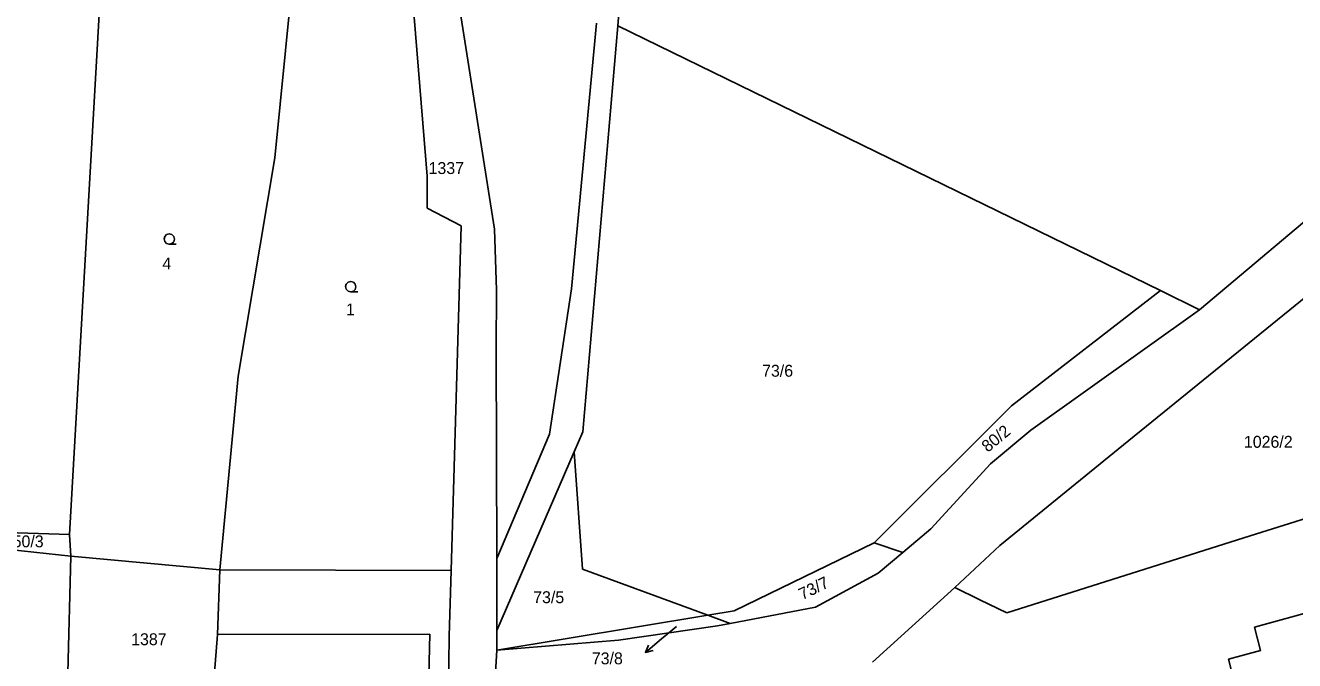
# Model space of a CAD drawing. Extents: x -852001 to -842497, y -1063614 to -1052182.
# Drawn here: x -844444 to -844262.9, y -1061413.7 to -1061323.1 of the extents above; entities that cross this region are included whole.
import ezdxf

# ---------------------------------------------------------------- set-up
doc = ezdxf.new("R2010")
doc.units = 0
for name, color, linetype in [('Default', 7, 'Continuous'), ('KN_HRANICE', 7, 'Continuous'), ('KN_KULTURY', 7, 'Continuous'), ('KN_PARCELY', 7, 'Continuous'), ('KN_SLUCKY', 7, 'Continuous')]:
    doc.layers.add(name, color=color, linetype=linetype)

# ---------------------------------------------------------------- blocks, each defined once
blk = doc.blocks.new('304')
at = {"layer": 'Default'}
blk.add_lwpolyline([(0, 0), (-0.38, 0.1), (-0.65, 0.37), (-0.75, 0.74), (-0.65, 1.11), (-0.38, 1.38), (-0.01, 1.48), (0.36, 1.38), (0.63, 1.11), (0.73, 0.73), (0.63, 0.35), (0.36, 0.08), (-0.02, -0.02), (0.98, -0.02)], dxfattribs=at)
blk = doc.blocks.new('10292')
at = {"layer": 'Default'}
blk.add_line((0, 3), (0, 0), dxfattribs=at)
blk.add_lwpolyline([(-0.5, 2), (0, 3), (0.5, 2)], dxfattribs=at)

msp = doc.modelspace()

# ---------------------------------------------------------------- linework, layer by layer
at = {"layer": 'KN_HRANICE'}
for p, q in [((-844355.8, -1061278.6), (-844359.49, -1061323.11)), ((-844355.8, -1061278.6), (-844359.49, -1061323.11)), ((-844437.76, -1061395.7), (-844432.89, -1061310.51)), ((-844437.76, -1061395.7), (-844432.89, -1061310.51)), ((-844408.43, -1061341.94), (-844405.53, -1061312.84)), ((-844408.43, -1061341.94), (-844405.53, -1061312.84)), ((-844389.08, -1061315.26), (-844386.69, -1061344.57)), ((-844389.08, -1061315.26), (-844386.69, -1061344.57)), ((-844377.08, -1061352.12), (-844382.88, -1061315.51)), ((-844377.08, -1061352.12), (-844382.88, -1061315.51)), ((-844362.55, -1061322.76), (-844366.12, -1061360.65)), ((-844362.55, -1061322.76), (-844366.12, -1061360.65)), ((-844359.49, -1061323.11), (-844364.48, -1061381.09)), ((-844359.49, -1061323.11), (-844364.48, -1061381.09)), ((-844282.06, -1061360.88), (-844359.49, -1061323.11)), ((-844282.06, -1061360.88), (-844359.49, -1061323.11)), ((-844276.49, -1061363.63), (-844241.6, -1061334.29)), ((-844276.49, -1061363.63), (-844241.6, -1061334.29)), ((-844413.69, -1061373.1), (-844408.43, -1061341.94)), ((-844413.69, -1061373.1), (-844408.43, -1061341.94)), ((-844386.69, -1061344.57), (-844386.69, -1061349.14)), ((-844386.69, -1061344.57), (-844386.69, -1061349.14)), ((-844386.69, -1061349.14), (-844381.84, -1061351.65)), ((-844386.69, -1061349.14), (-844381.84, -1061351.65)), ((-844381.84, -1061351.65), (-844383.28, -1061400.88)), ((-844381.84, -1061351.65), (-844383.28, -1061400.88)), ((-844376.79, -1061360.87), (-844377.08, -1061352.12)), ((-844376.79, -1061360.87), (-844377.08, -1061352.12)), ((-844255.48, -1061357.05), (-844287.3, -1061382.9)), ((-844255.48, -1061357.05), (-844287.3, -1061382.9)), ((-844376.86, -1061369.32), (-844376.79, -1061360.87)), ((-844376.86, -1061369.32), (-844376.79, -1061360.87)), ((-844366.12, -1061360.65), (-844369.26, -1061381.41)), ((-844366.12, -1061360.65), (-844369.26, -1061381.41)), ((-844282.06, -1061360.88), (-844303.29, -1061377.34)), ((-844282.06, -1061360.88), (-844303.29, -1061377.34)), ((-844282.06, -1061360.88), (-844276.49, -1061363.63)), ((-844282.06, -1061360.88), (-844276.49, -1061363.63)), ((-844300.54, -1061380.81), (-844276.49, -1061363.63)), ((-844300.54, -1061380.81), (-844276.49, -1061363.63)), ((-844376.78, -1061399.14), (-844376.86, -1061369.32)), ((-844376.78, -1061399.14), (-844376.86, -1061369.32)), ((-844416.28, -1061400.77), (-844413.69, -1061373.1)), ((-844416.28, -1061400.77), (-844413.69, -1061373.1)), ((-844303.29, -1061377.34), (-844322.91, -1061396.91)), ((-844303.29, -1061377.34), (-844322.91, -1061396.91)), ((-844306.31, -1061385.64), (-844300.54, -1061380.81)), ((-844306.31, -1061385.64), (-844300.54, -1061380.81)), ((-844369.26, -1061381.41), (-844376.78, -1061399.14)), ((-844369.26, -1061381.41), (-844376.78, -1061399.14)), ((-844364.48, -1061381.09), (-844365.7, -1061383.91)), ((-844364.48, -1061381.09), (-844365.7, -1061383.91)), ((-844365.7, -1061383.91), (-844376.75, -1061409.41)), ((-844365.7, -1061383.91), (-844376.75, -1061409.41)), ((-844365.7, -1061383.91), (-844364.51, -1061400.66)), ((-844365.7, -1061383.91), (-844364.51, -1061400.66)), ((-844287.3, -1061382.9), (-844304.99, -1061397.3)), ((-844287.3, -1061382.9), (-844304.99, -1061397.3)), ((-844314.83, -1061394.93), (-844306.31, -1061385.64)), ((-844314.83, -1061394.93), (-844306.31, -1061385.64)), ((-844234.19, -1061384.88), (-844269.23, -1061395.89)), ((-844234.19, -1061384.88), (-844269.23, -1061395.89)), ((-844475.97, -1061394.54), (-844437.76, -1061395.7)), ((-844437.56, -1061398.83), (-844475.97, -1061394.54)), ((-844475.97, -1061394.54), (-844437.76, -1061395.7)), ((-844437.56, -1061398.83), (-844475.97, -1061394.54)), ((-844318.83, -1061398.3), (-844314.83, -1061394.93)), ((-844318.83, -1061398.3), (-844314.83, -1061394.93)), ((-844437.56, -1061398.83), (-844437.76, -1061395.7)), ((-844437.56, -1061398.83), (-844437.76, -1061395.7)), ((-844322.91, -1061396.91), (-844342.88, -1061406.62)), ((-844322.91, -1061396.91), (-844342.88, -1061406.62)), ((-844322.91, -1061396.91), (-844318.83, -1061398.3)), ((-844322.91, -1061396.91), (-844318.83, -1061398.3)), ((-844269.23, -1061395.89), (-844303.98, -1061406.9)), ((-844269.23, -1061395.89), (-844303.98, -1061406.9)), ((-844438.01, -1061415.47), (-844437.56, -1061398.83)), ((-844438.01, -1061415.47), (-844437.56, -1061398.83)), ((-844437.56, -1061398.83), (-844416.28, -1061400.77)), ((-844437.56, -1061398.83), (-844416.28, -1061400.77)), ((-844322.33, -1061401.24), (-844318.83, -1061398.3)), ((-844322.33, -1061401.24), (-844318.83, -1061398.3)), ((-844304.99, -1061397.3), (-844311.38, -1061403.28)), ((-844304.99, -1061397.3), (-844311.38, -1061403.28)), ((-844416.28, -1061400.77), (-844416.62, -1061410.01)), ((-844416.28, -1061400.77), (-844416.62, -1061410.01)), ((-844416.28, -1061400.77), (-844383.28, -1061400.88)), ((-844416.28, -1061400.77), (-844383.28, -1061400.88)), ((-844376.75, -1061409.41), (-844376.78, -1061399.14)), ((-844376.75, -1061409.41), (-844376.78, -1061399.14)), ((-844364.51, -1061400.66), (-844346.64, -1061407.24)), ((-844364.51, -1061400.66), (-844346.64, -1061407.24)), ((-844383.28, -1061400.88), (-844383.55, -1061410.22)), ((-844383.28, -1061400.88), (-844383.55, -1061410.22)), ((-844331.28, -1061406.1), (-844322.33, -1061401.24)), ((-844331.28, -1061406.1), (-844322.33, -1061401.24)), ((-844311.38, -1061403.28), (-844323.12, -1061413.92)), ((-844311.38, -1061403.28), (-844323.12, -1061413.92)), ((-844307.8, -1061405.03), (-844311.38, -1061403.28)), ((-844307.8, -1061405.03), (-844311.38, -1061403.28)), ((-844343.46, -1061408.4), (-844331.28, -1061406.1)), ((-844343.46, -1061408.4), (-844331.28, -1061406.1)), ((-844303.98, -1061406.9), (-844307.8, -1061405.03)), ((-844303.98, -1061406.9), (-844307.8, -1061405.03)), ((-844346.64, -1061407.24), (-844376.75, -1061412.24)), ((-844346.64, -1061407.24), (-844376.75, -1061412.24)), ((-844342.88, -1061406.62), (-844346.64, -1061407.24)), ((-844342.88, -1061406.62), (-844346.64, -1061407.24)), ((-844346.64, -1061407.24), (-844343.46, -1061408.4)), ((-844346.64, -1061407.24), (-844343.46, -1061408.4)), ((-844259.62, -1061406.48), (-844268.64, -1061408.96)), ((-844259.62, -1061406.48), (-844268.64, -1061408.96)), ((-844376.75, -1061409.41), (-844376.75, -1061412.24)), ((-844376.75, -1061409.41), (-844376.75, -1061412.24)), ((-844359.4, -1061410.79), (-844345.26, -1061408.74)), ((-844359.4, -1061410.79), (-844345.26, -1061408.74)), ((-844345.26, -1061408.74), (-844343.46, -1061408.4)), ((-844345.26, -1061408.74), (-844343.46, -1061408.4)), ((-844267.77, -1061412.3), (-844268.64, -1061408.96)), ((-844267.77, -1061412.3), (-844268.64, -1061408.96)), ((-844416.62, -1061410.01), (-844417.56, -1061421.43)), ((-844416.62, -1061410.01), (-844417.56, -1061421.43)), ((-844383.55, -1061410.22), (-844383.68, -1061421.62)), ((-844383.55, -1061410.22), (-844383.68, -1061421.62)), ((-844376.75, -1061412.24), (-844359.4, -1061410.79)), ((-844376.75, -1061412.24), (-844359.4, -1061410.79)), ((-844377.11, -1061418.19), (-844376.75, -1061412.24)), ((-844377.11, -1061418.19), (-844376.75, -1061412.24)), ((-844272.32, -1061413.52), (-844267.77, -1061412.3)), ((-844272.32, -1061413.52), (-844267.77, -1061412.3)), ((-844271.7, -1061415.94), (-844272.32, -1061413.52)), ((-844271.7, -1061415.94), (-844272.32, -1061413.52))]:
    msp.add_line(p, q, dxfattribs=at)
at = {"layer": 'KN_PARCELY'}
msp.add_line((-844351.14, -1061408.83), (-844353.26, -1061410.62), dxfattribs=at)
msp.add_line((-844351.14, -1061408.83), (-844353.26, -1061410.62), dxfattribs=at)
at = {"layer": 'KN_SLUCKY'}
for p, q in [((-844386.31, -1061409.93), (-844416.62, -1061410.01)), ((-844386.31, -1061409.93), (-844416.62, -1061410.01)), ((-844386.59, -1061420.96), (-844386.31, -1061409.93)), ((-844386.59, -1061420.96), (-844386.31, -1061409.93))]:
    msp.add_line(p, q, dxfattribs=at)

# ---------------------------------------------------------------- block references
at = {"layer": 'KN_KULTURY'}
for p in [(-844423.51, -1061354.28), (-844423.51, -1061354.28), (-844397.6, -1061361.08), (-844397.6, -1061361.08)]:
    msp.add_blockref('304', p, dxfattribs=at)
at = {"layer": 'KN_PARCELY', "rotation": 130.061419}
msp.add_blockref('10292', (-844353.26, -1061410.62), dxfattribs=at)
msp.add_blockref('10292', (-844353.26, -1061410.62), dxfattribs=at)

# ---------------------------------------------------------------- texts
at = {"layer": 'KN_PARCELY'}
for s, height, p in [('1337', 1.7, (-844386.5, -1061344.27)), ('1337', 1.7, (-844386.5, -1061344.27)), ('4', 1.7, (-844424.5, -1061357.89)), ('4', 1.7, (-844424.5, -1061357.89)), ('1', 1.7, (-844398.29, -1061364.45)), ('1', 1.7, (-844398.29, -1061364.45)), ('73/6', 1.7, (-844338.9, -1061373.2)), ('73/6', 1.7, (-844338.9, -1061373.2)), ('1026/2', 1.7, (-844270.13, -1061383.34)), ('1026/2', 1.7, (-844270.13, -1061383.34)), ('250/3', 1.7, (-844447.13, -1061397.55)), ('250/3', 1.7, (-844447.13, -1061397.55)), ('73/5', 1.7, (-844371.57, -1061405.52)), ('73/5', 1.7, (-844371.57, -1061405.52)), ('1387', 1.7, (-844428.95, -1061411.52)), ('1387', 1.7, (-844428.95, -1061411.52)), ('73/8', 0.1, (-844351.34, -1061408.83)), ('73/8', 0.1, (-844351.34, -1061408.83)), ('73/8', 1.7, (-844363.2, -1061414.25)), ('73/8', 1.7, (-844363.2, -1061414.25))]:
    msp.add_text(s, height=height, dxfattribs=at).set_placement(p)
for s, rotation, p in [('80/2', 39.591, (-844306.69, -1061384.07)), ('80/2', 39.591, (-844306.69, -1061384.07)), ('73/7', 26.299, (-844333.15, -1061405.12)), ('73/7', 26.299, (-844333.15, -1061405.12))]:
    msp.add_text(s, height=1.7, rotation=rotation, dxfattribs=at).set_placement(p)

doc.saveas('drawing.dxf')
